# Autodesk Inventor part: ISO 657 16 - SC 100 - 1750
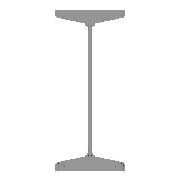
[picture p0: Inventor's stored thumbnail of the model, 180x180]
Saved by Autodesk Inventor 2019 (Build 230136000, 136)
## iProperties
_CCFamilyMember: 1
_CCFamilyDisplayName: ISO 657/16 - 1980 - Poutres en acier laminées à chaud - Partie 16: profilés en H (série métrique) - Cotes et propriétés de section
_FrameMemberDoc: Frame Member File
_Version: 15.0.0
_GetPNFromCC: 1
Created: 2018-07
Part Number: ISO 657 16 - SC 100 - 1750
Material: Acier, doux
Description: Poutres en acier laminées à chaud - Partie 16: profilés en H (série métrique) - Cotes et propriétés de section
Document SubType Name: Modeling
Standard: ISO
Designer: Fabian Perrée
Standard Revision: First edition 1980-02-15
Standards Organization: ISO
Language: fr-FR
Size Designation: SC 100
Categories: <MemberInstance><Categories><Category DisplayName="Profilés" InternalName="089c4875-fa83-4c05-b084-43b9cc11f5ed" Mnemonic="GRDR"><CategoryParameter DisplayName=
Stock Number: SC 100
Density: 7.85 g/cm^3
Appearance: Semi-poli
Mass: 33560.6 g
Surface Area: 9272.62 cm^2
Volume: 4275.24 cm^3
IsCustomPart: 1
G_W: 100,000 mm
G_H: 100,000 mm
G_L: 1750,000 mm
+03B31D45-75D1-422C-8BCC-0FAA0B7988AC+DETAILDECOUPE3: Grugeage
+DF01DF1C-54F0-4128-AB60-1988E2794DEE+DETAILDECOUPE4: Grugeage
Author: Fabian Perrée
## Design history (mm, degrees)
node "Plan de départ"
node "Plan de fin"
sketch "Esquisse"
  geometry: L1 (-3, 0)-(-3, -26.266); L2 (-13.33, -38.149)-(-44.835, -42.577); L3 (-50, -48.518)-(-50, -50); L4 (-50, -50)-(0, -50); L5 (-26.5, -50)-(-26.5, -40); L6 (-61.333, 0)-(81.777, 0); L7 (0, 0)-(0, -50); L8 (0, -60)-(0, 80); L9 (3, 0)-(3, -26.266); L10 (13.33, -38.149)-(44.835, -42.577); L11 (50, -48.518)-(50, -50); L12 (50, -50)-(0, -50); L13 (-3, 0)-(0, 0); L14 (-3, 0)-(-3, 26.266); L15 (-13.33, 38.149)-(-44.835, 42.577); L16 (-50, 48.518)-(-50, 50); L17 (-50, 50)-(0, 50); L18 (50, 48.518)-(50, 50); L19 (13.33, 38.149)-(44.835, 42.577); L20 (3, 0)-(3, 26.266); L21 (50, 50)-(0, 50); L22 (0, 108)-(0, -88) reference; L23 (-89.955, 0)-(110.399, 0) reference; A1 r 6 centre (-44, 48.518) between (-50, 48.518) and (-44.835, 42.577); A2 r 6 centre (44, 48.518) between (44.835, 42.577) and (50, 48.518); A3 r 6 centre (44, -48.518) between (50, -48.518) and (44.835, -42.577); A4 r 6 centre (-44, -48.518) between (-44.835, -42.577) and (-50, -48.518); A5 r 12 centre (-15, 26.266) between (-3, 26.266) and (-13.33, 38.149); A6 r 12 centre (15, 26.266) between (13.33, 38.149) and (3, 26.266); A7 r 12 centre (15, -26.266) between (3, -26.266) and (13.33, -38.149); A8 r 12 centre (-15, -26.266) between (-13.33, -38.149) and (-3, -26.266); 14 further points
  constraints: 42 end point, 24 point on line, 17 symmetric about line, 16 point on circle, 16 tangent, 8 centre point, 6 equal radius, 4 collinear, 2 perpendicular, 12 other
  dimensions: "d1" = 10 vertical distance of L3.end L5.end (= G_T1); "d2" = 23.5 distance between parallel lines of L5 L3 (= -0.25 x G_T + 0.25 x G_W); "d3" = 3 distance between parallel lines of L1 L7 (= 0.5 x G_T); "d4" = 50 distance between parallel lines of L7 L3 (= 0.5 x G_W); "d9" = 50 distance from line of L1.start L4 (= 0.5 x G_H); "d14" = 98 deg angle of L2 L1 (= G_NG); "d15" = 6 radius of A1 (= G_ER); "d16" = 12 radius of A5 (= G_IR)
extrude "Corps" new body sketch "Esquisse" stored distance "d5" = 1750 (= G_L); taper "d6" = 0 deg
node "Driven Length"
  sketch "Sketch3"
    geometry: L1 (0, 0)-(10, 0) reference
    constraints: 2 end point, 1 horizontal
  workplane "Work Plane3"
  sketch "Sketch4"
    geometry: L1 (-2, 0)-(12, 0) reference; L2 (-2, 1750)-(12, 1750) reference
    dimensions: "d20" = 1750 distance between parallel lines of L1 L2 (derived)
node "Plan de construction8"
node "Plan de construction9"
node "Plan de construction10"
sketch "Esquisse5"
  geometry: L1 (-3, 0)-(-3, -26.266); L2 (-13.33, -38.149)-(-44.835, -42.577); L3 (-50, -48.518)-(-50, -50); L4 (-50, -50)-(0, -50); L5 (50, -50)-(0, -50); L6 (50, -48.518)-(50, -50); L7 (13.33, -38.149)-(44.835, -42.577); L8 (3, 0)-(3, -26.266); L9 (3, 0)-(3, 26.266); L10 (13.33, 38.149)-(44.835, 42.577); L11 (50, 48.518)-(50, 50); L12 (50, 50)-(0, 50); L13 (-50, 50)-(0, 50); L14 (-50, 48.518)-(-50, 50); L15 (-13.33, 38.149)-(-44.835, 42.577); L16 (-3, 0)-(-3, 26.266); A1 r 12 centre (-15, -26.266) between (-13.33, -38.149) and (-3, -26.266); A2 r 6 centre (-44, -48.518) between (-44.835, -42.577) and (-50, -48.518); A3 r 6 centre (44, -48.518) between (50, -48.518) and (44.835, -42.577); A4 r 12 centre (15, -26.266) between (3, -26.266) and (13.33, -38.149); A5 r 12 centre (15, 26.266) between (13.33, 38.149) and (3, 26.266); A6 r 6 centre (44, 48.518) between (44.835, 42.577) and (50, 48.518); A7 r 6 centre (-44, 48.518) between (-50, 48.518) and (-44.835, 42.577); A8 r 12 centre (-15, 26.266) between (-3, 26.266) and (-13.33, 38.149)
  constraints: 32 end point, 16 point on circle, 8 centre point
extrude "Extrusion2" cut sketch "Esquisse5" stored distance "d21" = 0.13; taper "d22" = 0 deg
node "Plan de construction11"
node "Plan de construction12"
node "Plan de construction13"
sketch "Esquisse6"
  geometry: L1 (-3, 0)-(-3, -26.266); L2 (-13.33, -38.149)-(-44.835, -42.577); L3 (-50, -48.518)-(-50, -50); L4 (-50, -50)-(0, -50); L5 (50, -50)-(0, -50); L6 (50, -48.518)-(50, -50); L7 (13.33, -38.149)-(44.835, -42.577); L8 (3, 0)-(3, -26.266); L9 (3, 0)-(3, 26.266); L10 (13.33, 38.149)-(44.835, 42.577); L11 (50, 48.518)-(50, 50); L12 (50, 50)-(0, 50); L13 (-50, 50)-(0, 50); L14 (-50, 48.518)-(-50, 50); L15 (-13.33, 38.149)-(-44.835, 42.577); L16 (-3, 0)-(-3, 26.266); A1 r 12 centre (-15, -26.266) between (-13.33, -38.149) and (-3, -26.266); A2 r 6 centre (-44, -48.518) between (-44.835, -42.577) and (-50, -48.518); A3 r 6 centre (44, -48.518) between (50, -48.518) and (44.835, -42.577); A4 r 12 centre (15, -26.266) between (3, -26.266) and (13.33, -38.149); A5 r 12 centre (15, 26.266) between (13.33, 38.149) and (3, 26.266); A6 r 6 centre (44, 48.518) between (44.835, 42.577) and (50, 48.518); A7 r 6 centre (-44, 48.518) between (-50, 48.518) and (-44.835, 42.577); A8 r 12 centre (-15, 26.266) between (-3, 26.266) and (-13.33, 38.149)
  constraints: 32 end point, 16 point on circle, 8 centre point
extrude "Extrusion3" cut sketch "Esquisse6" stored distance "d23" = 0.13; taper "d24" = 0 deg
body "Solid1"
other parameters: "G_W" = 100 (= G_H) [user parameter; used in 2 equation terms], "G_H" = 100 [user parameter; used in 2 equation terms], "G_T" = 6 [user parameter; used in 2 equation terms], "G_T1" = 10 [user parameter; used in 1 equation term], "G_L" = 1750 (= d20) [user parameter; used in 1 equation term], "G_ER" = 6 [user parameter; used in 1 equation term], "G_IR" = 12 [user parameter; used in 1 equation term], "G_NG" = 98 deg [user parameter; used in 1 equation term], "G_OFFSET_START" = 0 [user parameter; used in 1 equation term], "G_OFFSET_END" = 0 [user parameter; used in 1 equation term], "d17" = 0 (computed from G_OFFSET_START), "d19" = 90 deg
